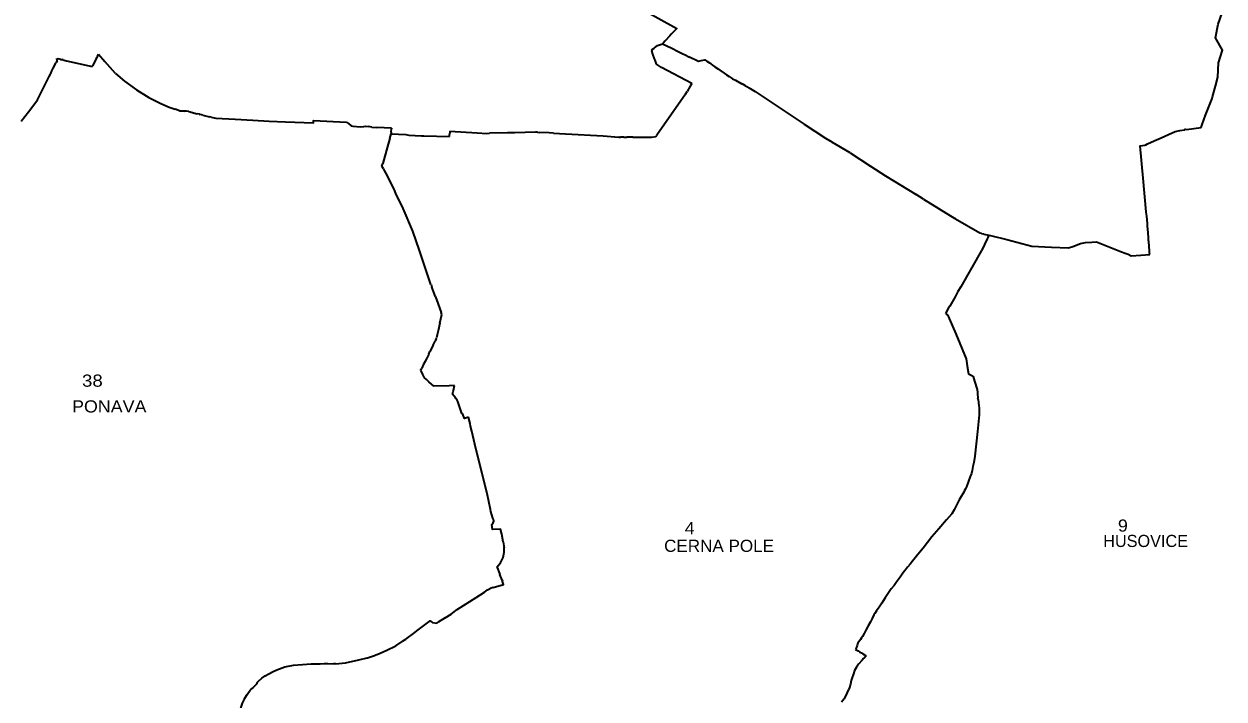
# Model space of a CAD drawing. Extents: x -610940 to -588976, y -1170376 to -1149800.
# Drawn here: x -598311 to -595840, y -1159152 to -1157762 of the extents above; entities that cross this region are included whole.
import ezdxf

# ---------------------------------------------------------------- set-up
doc = ezdxf.new("R2010")
doc.units = 0
doc.header["$LTSCALE"] = 10
doc.layers.add('54', color=7, linetype='Continuous', lineweight=35)
doc.layers.add('55', color=7, linetype='Continuous')
doc.layers.add('56', color=7, linetype='Continuous')

msp = doc.modelspace()

# ---------------------------------------------------------------- linework, layer by layer
at = {"layer": '54'}
for p, q in [((-598157.63, -1157824.55), (-598144.71, -1157839.14)), ((-597019.04, -1157815.74), (-597018.51, -1157817.25)), ((-597016.15, -1157824.02), (-597018.51, -1157817.25)), ((-596955.73, -1157822.65), (-596954.61, -1157823.25)), ((-596954.61, -1157823.25), (-596950.83, -1157825.13)), ((-596950.83, -1157825.13), (-596940.81, -1157830.11)), ((-598253.8, -1157858.64), (-598251.1, -1157853.27)), ((-598251.1, -1157853.27), (-598245.15, -1157841.36)), ((-598243.39, -1157837.9), (-598245.15, -1157841.36)), ((-598243.39, -1157837.9), (-598243.96, -1157832.97)), ((-598243.96, -1157832.97), (-598241.01, -1157833.67)), ((-598235.98, -1157834.87), (-598241.01, -1157833.67)), ((-598235.98, -1157834.87), (-598233.64, -1157835.41)), ((-598231.24, -1157835.95), (-598233.64, -1157835.41)), ((-598231.24, -1157835.95), (-598223.73, -1157837.73)), ((-598223.73, -1157837.73), (-598171.08, -1157849.54)), ((-598171.08, -1157849.54), (-598170.38, -1157848.22)), ((-598161.86, -1157832.18), (-598170.38, -1157848.22)), ((-598122.68, -1157863.87), (-598144.71, -1157839.14)), ((-597008.91, -1157845.03), (-597010.43, -1157840.37)), ((-596998.3, -1157851.97), (-597008.91, -1157845.03)), ((-596936.28, -1157884.53), (-596998.3, -1157851.97)), ((-596923.52, -1157838.69), (-596940.81, -1157830.11)), ((-596923.52, -1157838.69), (-596922.54, -1157838.74)), ((-598257.09, -1157865.22), (-598256.38, -1157863.8)), ((-598256.38, -1157863.8), (-598253.8, -1157858.64)), ((-596948.79, -1157906.62), (-596945.74, -1157901.23)), ((-596825.21, -1157889.63), (-596832.63, -1157885.27)), ((-596805.9, -1157900.96), (-596704.93, -1157968.67)), ((-598299.6, -1157939.84), (-598283.54, -1157918.62)), ((-596948.79, -1157906.62), (-597008.4, -1157991.4)), ((-598012.5, -1157933.07), (-598000.17, -1157937.76)), ((-597991.29, -1157941.16), (-598000.17, -1157937.76)), ((-597991.29, -1157941.16), (-597982.18, -1157941.2)), ((-597982.18, -1157941.2), (-597980.66, -1157941.4)), ((-597976.65, -1157941.95), (-597980.66, -1157941.4)), ((-597971.94, -1157942.59), (-597976.65, -1157941.95)), ((-597971.94, -1157942.59), (-597954.96, -1157946.86)), ((-597950.13, -1157948.1), (-597954.96, -1157946.86)), ((-597950.13, -1157948.1), (-597948.33, -1157948.56)), ((-597943, -1157949.92), (-597948.33, -1157948.56)), ((-597943, -1157949.92), (-597929.3, -1157953.44)), ((-597926.24, -1157954.22), (-597929.3, -1157953.44)), ((-597926.24, -1157954.22), (-597916.52, -1157955.94)), ((-597607.78, -1157972.19), (-597601.62, -1157973.48)), ((-597595.29, -1157974.81), (-597601.62, -1157973.48)), ((-597595.29, -1157974.81), (-597584.73, -1157975.26)), ((-597554.76, -1157976.56), (-597584.73, -1157975.26)), ((-597555.25, -1157984.88), (-597554.83, -1157977.76)), ((-597554.76, -1157976.56), (-597554.83, -1157977.76)), ((-596704.93, -1157968.67), (-596660.47, -1157997.34)), ((-595917.01, -1157979.54), (-595887.18, -1157974.98)), ((-597558.81, -1158000.2), (-597562.78, -1158014.26)), ((-597558.19, -1157998.03), (-597558.81, -1158000.2)), ((-597558.19, -1157998.03), (-597555.46, -1157988.41)), ((-597555.25, -1157984.88), (-597555.46, -1157988.41)), ((-597434.95, -1157993.82), (-597434.87, -1157991.82)), ((-597434.87, -1157991.82), (-597434.68, -1157986.83)), ((-597434.54, -1157983.04), (-597434.68, -1157986.83)), ((-597434.54, -1157983.04), (-597378.18, -1157986.18)), ((-597378.18, -1157986.18), (-597357.98, -1157987.3)), ((-597357.98, -1157987.3), (-597352.82, -1157987.19)), ((-597315.31, -1157986.36), (-597352.82, -1157987.19)), ((-597300.38, -1157986.02), (-597315.31, -1157986.36)), ((-597257.93, -1157985.08), (-597300.38, -1157986.02)), ((-597254, -1157984.99), (-597257.93, -1157985.08)), ((-597254, -1157984.99), (-597248.78, -1157985.26)), ((-597230.02, -1157986.24), (-597248.78, -1157985.26)), ((-597220.69, -1157986.72), (-597230.02, -1157986.24)), ((-597118.67, -1157992.7), (-597086.16, -1157995.34)), ((-597085.57, -1157995.39), (-597086.16, -1157995.34)), ((-597085.57, -1157995.39), (-597083.13, -1157995.34)), ((-597075.72, -1157995.2), (-597083.13, -1157995.34)), ((-597075.72, -1157995.2), (-597069.57, -1157995.2)), ((-597057.34, -1157995.2), (-597069.57, -1157995.2)), ((-597057.34, -1157995.2), (-597018.88, -1157995.01)), ((-597018.88, -1157995.01), (-597010.26, -1157994.04)), ((-597010.26, -1157994.04), (-597008.4, -1157991.4)), ((-596660.47, -1157997.34), (-596647.88, -1158004.75)), ((-595997.42, -1158008.95), (-595977.7, -1158000.12)), ((-595977.7, -1158000.12), (-595975.68, -1157999.16)), ((-595975.68, -1157999.16), (-595940.73, -1157983.28)), ((-595940.73, -1157983.28), (-595930.91, -1157981.66)), ((-595930.91, -1157981.66), (-595920.73, -1157980.1)), ((-597562.78, -1158014.26), (-597572.67, -1158049.25)), ((-597574.34, -1158055.17), (-597572.67, -1158049.25)), ((-597570.98, -1158060.5), (-597574.34, -1158055.17)), ((-597570.98, -1158060.5), (-597569.62, -1158062.65)), ((-597568.85, -1158063.88), (-597569.62, -1158062.65)), ((-596537.09, -1158074.85), (-596474.31, -1158113.21)), ((-596000.1, -1158148.74), (-596006.39, -1158079.5)), ((-596458.88, -1158122.66), (-596474.31, -1158113.21)), ((-596458.88, -1158122.66), (-596394.22, -1158163.01)), ((-596000, -1158149.83), (-596000.1, -1158148.74)), ((-595999.28, -1158157.65), (-596000, -1158149.83)), ((-596393.22, -1158163.61), (-596394.22, -1158163.01)), ((-596338.49, -1158193.7), (-596334.65, -1158194.61)), ((-596324.04, -1158197.14), (-596326.32, -1158201.81)), ((-596327.69, -1158204.61), (-596338.64, -1158227.67)), ((-596326.32, -1158201.81), (-596327.69, -1158204.61)), ((-596195.27, -1158221.68), (-596160.05, -1158223.44)), ((-596160.05, -1158223.44), (-596151.07, -1158220.25)), ((-596151.07, -1158220.25), (-596135.37, -1158214.48)), ((-596135.37, -1158214.48), (-596125.2, -1158211.93)), ((-596125.2, -1158211.93), (-596112.08, -1158211.13)), ((-596112.08, -1158211.13), (-596102.33, -1158210.54)), ((-596102.33, -1158210.54), (-596051.03, -1158231.49)), ((-596339.25, -1158228.73), (-596382.14, -1158303.33)), ((-596338.64, -1158227.67), (-596339.25, -1158228.73)), ((-596051.03, -1158231.49), (-596043.81, -1158233.96)), ((-596043.81, -1158233.96), (-596037.48, -1158236.23)), ((-596037.48, -1158236.23), (-596030.9, -1158239.94)), ((-596030.9, -1158239.94), (-596011.56, -1158238.41)), ((-596011.56, -1158238.41), (-595993.1, -1158236.95)), ((-597473.22, -1158298.44), (-597473.05, -1158298.89)), ((-597473.05, -1158298.89), (-597471.14, -1158303.96)), ((-597466.4, -1158316.57), (-597471.14, -1158303.96)), ((-597464.38, -1158322.5), (-597466.4, -1158316.57)), ((-597464.38, -1158322.5), (-597461.76, -1158329.81)), ((-596393.91, -1158323.96), (-596404.95, -1158342.94)), ((-596390.11, -1158317.26), (-596393.91, -1158323.96)), ((-596387.86, -1158313.3), (-596390.11, -1158317.26)), ((-596382.14, -1158303.33), (-596387.86, -1158313.3)), ((-597461.76, -1158329.81), (-597452.24, -1158356.44)), ((-596407.2, -1158346.88), (-596413.86, -1158358.4)), ((-596404.95, -1158342.94), (-596407.2, -1158346.88)), ((-597454.88, -1158378.21), (-597450.76, -1158360.58)), ((-597450.76, -1158360.58), (-597452.24, -1158356.44)), ((-596413.86, -1158358.4), (-596411.64, -1158359.85)), ((-596411.64, -1158359.85), (-596409.95, -1158360.76)), ((-596409.95, -1158360.76), (-596409.42, -1158361.04)), ((-596409.42, -1158361.04), (-596407.75, -1158364.95)), ((-596407.75, -1158364.95), (-596406.28, -1158368.4)), ((-596406.28, -1158368.4), (-596392.57, -1158400.57)), ((-597468.65, -1158423.34), (-597464.54, -1158415.05)), ((-597464.33, -1158414.63), (-597464.54, -1158415.05)), ((-597462.54, -1158411.01), (-597464.33, -1158414.63)), ((-597462.54, -1158411.01), (-597461.94, -1158408.44)), ((-597460.58, -1158402.62), (-597461.94, -1158408.44)), ((-596392.57, -1158400.57), (-596370.86, -1158451.49)), ((-597477.9, -1158441.98), (-597475.39, -1158436.92)), ((-597468.65, -1158423.34), (-597475.39, -1158436.92)), ((-597493.55, -1158473.31), (-597492.34, -1158470.88)), ((-597488.39, -1158462.97), (-597492.34, -1158470.88)), ((-597485.52, -1158457.23), (-597488.39, -1158462.97)), ((-597485.22, -1158456.64), (-597485.52, -1158457.23)), ((-596370.86, -1158451.49), (-596368.89, -1158466.21)), ((-596368.89, -1158466.21), (-596368.79, -1158466.84)), ((-596368.79, -1158466.84), (-596366.31, -1158482.38)), ((-597494.35, -1158474.91), (-597493.55, -1158473.31)), ((-597489.87, -1158483.85), (-597494.35, -1158474.91)), ((-597488.43, -1158486.83), (-597489.87, -1158483.85)), ((-597486.99, -1158489.71), (-597488.43, -1158486.83)), ((-597486.92, -1158489.94), (-597486.99, -1158489.71)), ((-597482.66, -1158494), (-597486.92, -1158489.94)), ((-597477.38, -1158499.05), (-597482.66, -1158494)), ((-596366.31, -1158482.38), (-596358.31, -1158487)), ((-596358.31, -1158487), (-596356.58, -1158487.94)), ((-596356.58, -1158487.94), (-596353.7, -1158497.6)), ((-597467.54, -1158508.32), (-597477.38, -1158499.05)), ((-597435.95, -1158507.31), (-597467.54, -1158508.32)), ((-597425.03, -1158506.96), (-597435.95, -1158507.31)), ((-597426.42, -1158513.73), (-597425.03, -1158506.96)), ((-596353.7, -1158497.6), (-596348.68, -1158515.04)), ((-596348.68, -1158515.04), (-596348.01, -1158521.44)), ((-596348.01, -1158521.44), (-596347.96, -1158522)), ((-597422.21, -1158533.22), (-597423.04, -1158532.06)), ((-597419.57, -1158536.94), (-597422.21, -1158533.22)), ((-596347.96, -1158522), (-596347.84, -1158523.44)), ((-596347.84, -1158523.44), (-596346.74, -1158533)), ((-596346.59, -1158535.25), (-596346.74, -1158533)), ((-596346.59, -1158535.25), (-596344.92, -1158548.65)), ((-596344.12, -1158566.97), (-596347.53, -1158601.56)), ((-596344.92, -1158548.65), (-596344.22, -1158552.79)), ((-596344.22, -1158552.79), (-596344.12, -1158566.97)), ((-596347.53, -1158601.56), (-596352.98, -1158652.59)), ((-596355.54, -1158665.22), (-596357.24, -1158673.55)), ((-596352.98, -1158652.59), (-596355.54, -1158665.22)), ((-596362.6, -1158693.96), (-596366.22, -1158703.57)), ((-596362.04, -1158692.57), (-596362.6, -1158693.96)), ((-596360.03, -1158687.63), (-596362.04, -1158692.57)), ((-596358.85, -1158681.7), (-596360.03, -1158687.63)), ((-596357.24, -1158673.55), (-596358.85, -1158681.7)), ((-596370.6, -1158715.18), (-596372.28, -1158719.64)), ((-596366.22, -1158703.57), (-596370.6, -1158715.18)), ((-596385.24, -1158742.46), (-596390.04, -1158751.48)), ((-596383.24, -1158738.97), (-596385.24, -1158742.46)), ((-596375.91, -1158726.1), (-596383.24, -1158738.97)), ((-596374.12, -1158722.89), (-596375.91, -1158726.1)), ((-596372.28, -1158719.64), (-596374.12, -1158722.89)), ((-596396, -1158762.65), (-596400.6, -1158771.11)), ((-596390.04, -1158751.48), (-596396, -1158762.65)), ((-596411.39, -1158783.31), (-596427.55, -1158801.68)), ((-596400.6, -1158771.11), (-596411.39, -1158783.31)), ((-596427.55, -1158801.68), (-596441.41, -1158818.67)), ((-597323.1, -1158838.65), (-597322.77, -1158841.36)), ((-597322.75, -1158850.31), (-597322.77, -1158841.36)), ((-596459.88, -1158841.53), (-596470.33, -1158854.46)), ((-596441.41, -1158818.67), (-596459.88, -1158841.53)), ((-596473.46, -1158858.39), (-596481.48, -1158868.32)), ((-596470.83, -1158855.1), (-596473.46, -1158858.39)), ((-596470.33, -1158854.46), (-596470.83, -1158855.1)), ((-597336.97, -1158881.82), (-597337.64, -1158881.02)), ((-597336.97, -1158881.82), (-597332.09, -1158894.15)), ((-596497.12, -1158888.01), (-596502.59, -1158895.53)), ((-596495.97, -1158886.56), (-596497.12, -1158888.01)), ((-596491.62, -1158881), (-596495.97, -1158886.56)), ((-596486.44, -1158874.67), (-596491.62, -1158881)), ((-596481.48, -1158868.32), (-596486.44, -1158874.67)), ((-597332.09, -1158894.15), (-597331.37, -1158895.98)), ((-597326.76, -1158907.63), (-597331.37, -1158895.98)), ((-597326.76, -1158907.63), (-597325.94, -1158909.79)), ((-597325.71, -1158910.4), (-597325.94, -1158909.79)), ((-596515.11, -1158912.72), (-596519.62, -1158918.88)), ((-596510.95, -1158907), (-596515.11, -1158912.72)), ((-596506.79, -1158901.27), (-596510.95, -1158907)), ((-596502.59, -1158895.53), (-596506.79, -1158901.27)), ((-597380.27, -1158943.12), (-597363.27, -1158932.19)), ((-597351.48, -1158925.09), (-597351.03, -1158924.91)), ((-597345.41, -1158922.67), (-597351.03, -1158924.91)), ((-596530.82, -1158933.51), (-596537.89, -1158944.29)), ((-596525.33, -1158925.52), (-596530.82, -1158933.51)), ((-596519.62, -1158918.88), (-596525.33, -1158925.52)), ((-597419.36, -1158968.24), (-597380.27, -1158943.12)), ((-596550.39, -1158963.28), (-596555.63, -1158971.01)), ((-596544.86, -1158954.87), (-596550.39, -1158963.28)), ((-596537.89, -1158944.29), (-596544.86, -1158954.87)), ((-597443.97, -1158985.07), (-597458.24, -1158994.23)), ((-597422.14, -1158970.21), (-597419.36, -1158968.24)), ((-596564.77, -1158986.68), (-596568.38, -1158993.32)), ((-596560.88, -1158979.4), (-596564.77, -1158986.68)), ((-596558.93, -1158976.03), (-596560.88, -1158979.4)), ((-596555.63, -1158971.01), (-596558.93, -1158976.03)), ((-596577.55, -1159010.52), (-596581.39, -1159017.58)), ((-596572.97, -1159001.87), (-596577.55, -1159010.52)), ((-596568.38, -1158993.32), (-596572.97, -1159001.87)), ((-597545.32, -1159042.64), (-597532.64, -1159034.33)), ((-597525.53, -1159029.66), (-597532.64, -1159034.33)), ((-597525.53, -1159029.66), (-597522.28, -1159027.26)), ((-596594.82, -1159039.05), (-596595.55, -1159042.11)), ((-596594.57, -1159038.55), (-596594.82, -1159039.05)), ((-596593.96, -1159037.72), (-596594.57, -1159038.55)), ((-596588.53, -1159029.86), (-596593.96, -1159037.72)), ((-596586.43, -1159026.71), (-596588.53, -1159029.86)), ((-596584.52, -1159023.91), (-596586.43, -1159026.71)), ((-596581.39, -1159017.58), (-596584.52, -1159023.91)), ((-596597.61, -1159047.89), (-596598.64, -1159050.33)), ((-596598.64, -1159050.33), (-596593.79, -1159053.21)), ((-596595.55, -1159042.11), (-596597.61, -1159047.89)), ((-596593.79, -1159053.21), (-596593.21, -1159053.56)), ((-596593.21, -1159053.56), (-596589.86, -1159055.71)), ((-596589.86, -1159055.71), (-596586.79, -1159057.52)), ((-596586.79, -1159057.52), (-596583.61, -1159059.45)), ((-596583.61, -1159059.45), (-596580.56, -1159061.36)), ((-596577.27, -1159063.84), (-596581.84, -1159068.76)), ((-596580.56, -1159061.36), (-596578.03, -1159062.9)), ((-596578.03, -1159062.9), (-596577.02, -1159063.42)), ((-596577.02, -1159063.42), (-596577.27, -1159063.84)), ((-597685.69, -1159079.62), (-597674, -1159079.72)), ((-597669.85, -1159079.76), (-597674, -1159079.72)), ((-596585.09, -1159072.2), (-596592.85, -1159080.77)), ((-596607.55, -1159114.24), (-596609.37, -1159121.72)), ((-596606.41, -1159110.48), (-596607.55, -1159114.24)), ((-596611.31, -1159128.91), (-596612.95, -1159131.85)), ((-596611.02, -1159128.42), (-596611.31, -1159128.91)), ((-596609.37, -1159121.72), (-596611.02, -1159128.42)), ((-596622.61, -1159151.93), (-596627.61, -1159158.97)), ((-596620.79, -1159149.52), (-596622.61, -1159151.93))]:
    msp.add_line(p, q, dxfattribs=at)
for points in [[(-597049.2, -1157723.15), (-597044.46, -1157727.97), (-597043.91, -1157728.55), (-596966.85, -1157771.12), (-596978.3, -1157783.32), (-596981.07, -1157786.27), (-596991, -1157796.97)], [(-595887.18, -1157974.98), (-595885.15, -1157969.15), (-595878.46, -1157949.97), (-595864.39, -1157915.54), (-595863.38, -1157911.89), (-595857.45, -1157890.31), (-595852.45, -1157871.79), (-595851.39, -1157842.37), (-595842.87, -1157815.92), (-595857.78, -1157790.59), (-595852.27, -1157762.24), (-595840.03, -1157727.17)], [(-597019.04, -1157815.74), (-597017.92, -1157814.85), (-597014.28, -1157812.24), (-597013.13, -1157811.33), (-597006.77, -1157806.57), (-596996.65, -1157803.27)], [(-596991, -1157796.97), (-596991.36, -1157797.34), (-596994.67, -1157800.77), (-596995.29, -1157801.49), (-596996.65, -1157803.27)], [(-596996.65, -1157803.27), (-596977.28, -1157811.7), (-596963.82, -1157818.57), (-596955.73, -1157822.65)], [(-598161.86, -1157832.18), (-598161.19, -1157830.95), (-598160.05, -1157828.86), (-598157.63, -1157824.55)], [(-597010.43, -1157840.37), (-597011.76, -1157836.5), (-597012.71, -1157833.75), (-597016.15, -1157824.02)], [(-596922.54, -1157838.74), (-596916.6, -1157837.41), (-596909.04, -1157835.82), (-596905.14, -1157838.62), (-596899.96, -1157842.21), (-596893.6, -1157846.64), (-596888.63, -1157850.05), (-596881.32, -1157855.1), (-596878.64, -1157856.92), (-596869.52, -1157863.06), (-596864.42, -1157866.62), (-596859.2, -1157870.12), (-596854.67, -1157873.08), (-596852.01, -1157874.9)], [(-598283.54, -1157918.62), (-598259.71, -1157870.51), (-598257.09, -1157865.22)], [(-598122.68, -1157863.87), (-598104.45, -1157879.57), (-598079.96, -1157898.01), (-598054.12, -1157913.19), (-598029.66, -1157925.59), (-598012.5, -1157933.07)], [(-596852.01, -1157874.9), (-596846.2, -1157877.83), (-596833.22, -1157885.01), (-596832.63, -1157885.27)], [(-596936.28, -1157884.53), (-596939.31, -1157889.88), (-596945.74, -1157901.23)], [(-596825.21, -1157889.63), (-596824.18, -1157890.24), (-596816.87, -1157894.53), (-596815.93, -1157895.08), (-596808.71, -1157899.31), (-596805.9, -1157900.96)], [(-598317.07, -1157962.13), (-598302.01, -1157943.02), (-598299.6, -1157939.84)], [(-597916.52, -1157955.94), (-597876.49, -1157958.14), (-597840.45, -1157960.16), (-597806.48, -1157961.96), (-597773.01, -1157963.48), (-597715.29, -1157965.81), (-597715, -1157960.88), (-597647.27, -1157964.3)], [(-597647.27, -1157964.3), (-597643.41, -1157967.16), (-597637.45, -1157971.56)], [(-597637.45, -1157971.56), (-597634.19, -1157972.24), (-597618.32, -1157973.8), (-597611.45, -1157973.43), (-597607.78, -1157972.19)], [(-597555.46, -1157988.41), (-597525.28, -1157989.41), (-597518.83, -1157991.27), (-597493.06, -1157992.38), (-597488.04, -1157992.7), (-597434.95, -1157993.82)], [(-597220.69, -1157986.72), (-597196.08, -1157988.21), (-597118.67, -1157992.7)], [(-595920.73, -1157980.1), (-595920.15, -1157978.43), (-595917.01, -1157979.54)], [(-596609.9, -1158027.11), (-596646.04, -1158005.83), (-596647.88, -1158004.75)], [(-596609.9, -1158027.11), (-596567.84, -1158054.69), (-596537.09, -1158074.85)], [(-596006.39, -1158079.5), (-596012.65, -1158013.02), (-596003.26, -1158011.33), (-596000.98, -1158010.86), (-595997.42, -1158008.95)], [(-597496.83, -1158228.53), (-597510.58, -1158188.71), (-597530.83, -1158142.01), (-597545.63, -1158111.09), (-597549.15, -1158102.47), (-597565.95, -1158068.43), (-597568.85, -1158063.88)], [(-596393.22, -1158163.61), (-596343.06, -1158192.5), (-596340.32, -1158193.22)], [(-595995.38, -1158207.24), (-595995.48, -1158205.86), (-595995.73, -1158202), (-595997.1, -1158184.27), (-595997.39, -1158179.39), (-595997.8, -1158174.05), (-595997.9, -1158172.88), (-595999.28, -1158157.65)], [(-596340.32, -1158193.22), (-596339.7, -1158193.38), (-596338.49, -1158193.7)], [(-596334.65, -1158194.61), (-596334.34, -1158194.69), (-596324.04, -1158197.14)], [(-596324.04, -1158197.14), (-596320.93, -1158198.01), (-596287.45, -1158206.06), (-596235.49, -1158219.68), (-596195.27, -1158221.68)], [(-595993.1, -1158236.95), (-595993.35, -1158233.63), (-595993.67, -1158229.27), (-595995.11, -1158211.08), (-595995.38, -1158207.24)], [(-597473.22, -1158298.44), (-597490.42, -1158246.97), (-597496.83, -1158228.53)], [(-597454.88, -1158378.21), (-597458.54, -1158393.87), (-597460.58, -1158402.62)], [(-597477.9, -1158441.98), (-597482.75, -1158451.69), (-597485.22, -1158456.64)], [(-597423.04, -1158532.06), (-597428.57, -1158524.3), (-597427.54, -1158519.25)], [(-597427.54, -1158519.25), (-597427.12, -1158517.17), (-597426.42, -1158513.73)], [(-597408.18, -1158564.19), (-597409.36, -1158564.63), (-597417.76, -1158539.49), (-597419.57, -1158536.94)], [(-597395.85, -1158571.91), (-597404.15, -1158574.87), (-597408.18, -1158564.19)], [(-597380.2, -1158639.05), (-597382.92, -1158627.38), (-597389.2, -1158600.83), (-597391.54, -1158590.68), (-597392.86, -1158585.03), (-597395.85, -1158571.91)], [(-597324.42, -1158828.74), (-597327.37, -1158813.09), (-597329.73, -1158802.3), (-597330.27, -1158802.42), (-597346.46, -1158803.2), (-597347.69, -1158793.15), (-597345.23, -1158789.81), (-597344.04, -1158786.05), (-597344.62, -1158782.37), (-597345.52, -1158779.89), (-597347.89, -1158773.12), (-597349.68, -1158766.3), (-597350.45, -1158762.28), (-597357.81, -1158729.19), (-597380.2, -1158639.05)], [(-597324.42, -1158828.74), (-597323.32, -1158836.86), (-597323.1, -1158838.65)], [(-597337.64, -1158881.02), (-597329.85, -1158872.23), (-597324.78, -1158861.19), (-597322.75, -1158850.31)], [(-597345.41, -1158922.67), (-597323.7, -1158916.87), (-597325.71, -1158910.4)], [(-597363.27, -1158932.19), (-597356.77, -1158927.79), (-597354.38, -1158926.4), (-597351.48, -1158925.09)], [(-597443.97, -1158985.07), (-597431.98, -1158977.72), (-597425.21, -1158972.63), (-597422.14, -1158970.21)], [(-597522.28, -1159027.26), (-597509.4, -1159017.73), (-597499.52, -1159010.14)], [(-597499.52, -1159010.14), (-597475.11, -1158991.45), (-597472.15, -1158992.48)], [(-597472.15, -1158992.48), (-597470.2, -1158994.75), (-597461.28, -1158996.14), (-597458.24, -1158994.23)], [(-597669.85, -1159079.76), (-597649.42, -1159078.12), (-597621.74, -1159072.1), (-597604.32, -1159067.34), (-597604.2, -1159067.57), (-597589.81, -1159062.76), (-597586.54, -1159061.53), (-597582.5, -1159059.78), (-597565.48, -1159052.47), (-597545.32, -1159042.64)], [(-597807.09, -1159100.42), (-597798.44, -1159095.98), (-597790.91, -1159092.34), (-597784.85, -1159090.08), (-597773.91, -1159086.34)], [(-597773.91, -1159086.34), (-597756.12, -1159082.91), (-597737.82, -1159081.13), (-597719.94, -1159080.29), (-597712.1, -1159080.06), (-597711.68, -1159080.06), (-597709.81, -1159080), (-597709.45, -1159079.99), (-597701.16, -1159079.78)], [(-597701.16, -1159079.78), (-597693.04, -1159079.6), (-597685.69, -1159079.62)], [(-596592.85, -1159080.77), (-596596.81, -1159086.97), (-596600.82, -1159093.43), (-596603.27, -1159100.68), (-596606.41, -1159110.48)], [(-596581.84, -1159068.76), (-596582.27, -1159069.21), (-596585.09, -1159072.2)], [(-597828.25, -1159115.59), (-597821.27, -1159109.82), (-597814.45, -1159104.71), (-597807.09, -1159100.42)], [(-597867.18, -1159179.21), (-597865.19, -1159171.22), (-597864.45, -1159169.14), (-597861.57, -1159161.34), (-597857.57, -1159152.79), (-597856.58, -1159150.73), (-597852.01, -1159143.19), (-597845.76, -1159134.55), (-597844.72, -1159133.33), (-597844.44, -1159133.09), (-597838.9, -1159128.61), (-597838.69, -1159128.4)], [(-597838.69, -1159128.4), (-597832.64, -1159122.13), (-597832.44, -1159121.91), (-597830.88, -1159120.48), (-597831.96, -1159119.17), (-597828.25, -1159115.59)], [(-596612.95, -1159131.85), (-596613.51, -1159133.04), (-596616.09, -1159138.76), (-596620.79, -1159149.52)]]:
    msp.add_lwpolyline(points, dxfattribs=at)

# ---------------------------------------------------------------- texts
at = {"layer": '55'}
for s, width, p in [('PONAVA ', 1.1, (-598212.44, -1158562.23)), ('CERNA POLE', 1.05, (-596993.09, -1158849.38))]:
    msp.add_text(s, height=25, dxfattribs=dict(at, width=width)).set_placement(p)
msp.add_text('HUSOVICE ', height=25, dxfattribs=at).set_placement((-596088.74, -1158839.37))
at = {"layer": '56'}
for s, width, p in [('38 ', 1.15, (-598191.92, -1158509.18)), ('4 ', 1.1, (-596950.62, -1158812.97)), ('9 ', 1.1, (-596058.48, -1158807.72))]:
    msp.add_text(s, height=25, dxfattribs=dict(at, width=width)).set_placement(p)

doc.saveas('drawing.dxf')
